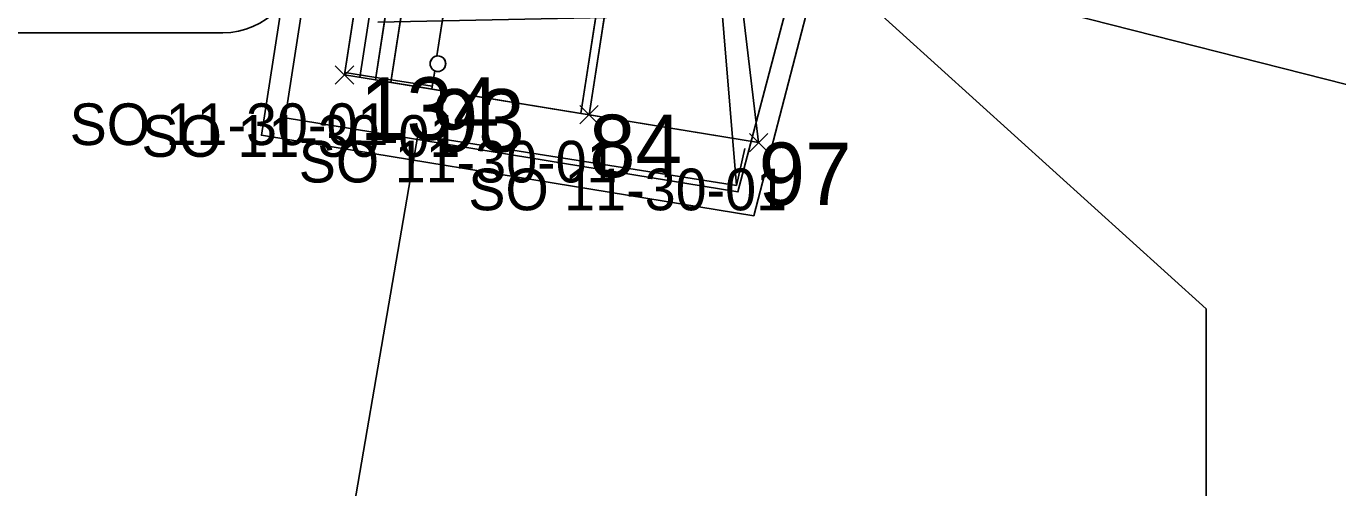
# Model space of a CAD drawing. Extents: x -728800 to -728100, y -1073200 to -1072700.
# Drawn here: x -728506.62 to -728494.02, y -1073056.81 to -1073052.38 of the extents above; entities that cross this region are included whole.
import ezdxf

# ---------------------------------------------------------------- set-up
doc = ezdxf.new("R2010")
doc.units = 0
for name, color, linetype in [('_NOR-návrh tenká', 7, 'Continuous'), ('_NOR-VDZ', 7, 'Continuous'), ('_NOR-šraf_+6', 7, 'Continuous'), ('_NOR-šraf_bezbariéra', 7, 'Continuous'), ('_NOR-šraf_chodník', 7, 'Continuous'), ('_NOR-šraf_varovný pás', 7, 'Continuous'), ('_NOR-šraf_vozovka', 7, 'Continuous'), ('_NOR-šraf_zeleň', 7, 'Continuous'), ('A1_OBVOD Spravy železnic', 7, 'Continuous'), ('A2_OBVOD STAVBY', 7, 'Continuous'), ('B1_body_poloha', 7, 'Continuous'), ('B2_body_číslo', 7, 'Continuous'), ('B3_body_popiska', 7, 'Continuous'), ('B6_JŽM', 7, 'Continuous'), ('KTA_členění PS a SO', 7, 'Continuous'), ('ZA_02_Dočasný_do_1_roku', 7, 'Continuous')]:
    doc.layers.add(name, color=color, linetype=linetype)

msp = doc.modelspace()

# ---------------------------------------------------------------- linework, layer by layer
at = {"layer": '_NOR-návrh tenká'}
for p, q in [((-728499.581, -1073053.497), (-728499.904, -1073050.807)), ((-728503.263, -1073052.895), (-728503.559, -1073052.847)), ((-728499.581, -1073053.497), (-728503.263, -1073052.895))]:
    msp.add_line(p, q, dxfattribs=at)
for points in [[(-728502.819, -1073048.076), (-728503.559, -1073052.847)], [(-728502.523, -1073048.119), (-728503.263, -1073052.895)], [(-728502.374, -1073048.141), (-728503.115, -1073052.92)], [(-728500.544, -1073048.409), (-728501.289, -1073053.218)], [(-728500.465, -1073048.422), (-728501.21, -1073053.23)], [(-728502.31, -1073050.336), (-728502.671, -1073052.666)], [(-728502.693, -1073052.808), (-728502.721, -1073052.984)]]:
    msp.add_lwpolyline(points, dxfattribs=at)
msp.add_circle((-728502.662, -1073052.74), 0.075, dxfattribs=at)
at = {"layer": '_NOR-VDZ'}
msp.add_lwpolyline([(-728502.671, -1073048.097), (-728503.411, -1073052.871)], dxfattribs=at)
at = {"layer": '_NOR-šraf_+6'}
for p, q in [((-728500.465, -1073048.422), (-728501.21, -1073053.231)), ((-728501.289, -1073053.218), (-728500.958, -1073051.084)), ((-728501.21, -1073053.231), (-728501.289, -1073053.218))]:
    msp.add_line(p, q, dxfattribs=at)
at = {"layer": '_NOR-šraf_bezbariéra'}
for p, q in [((-728503.259, -1073052.871), (-728502.523, -1073048.119)), ((-728502.374, -1073048.141), (-728503.111, -1073052.894)), ((-728503.111, -1073052.894), (-728503.259, -1073052.871)), ((-728503.259, -1073052.871), (-728503.111, -1073052.894))]:
    msp.add_line(p, q, dxfattribs=at)
msp.add_lwpolyline([(-728503.111, -1073052.894), (-728503.115, -1073052.92), (-728503.229, -1073052.901), (-728503.263, -1073052.895), (-728503.259, -1073052.871)], dxfattribs=at)
at = {"layer": '_NOR-šraf_chodník'}
for p, q in [((-728502.671, -1073052.666), (-728502.31, -1073050.336)), ((-728500.994, -1073051.315), (-728501.289, -1073053.218)), ((-728502.721, -1073052.984), (-728502.693, -1073052.808)), ((-728501.289, -1073053.218), (-728502.721, -1073052.984))]:
    msp.add_line(p, q, dxfattribs=at)
msp.add_arc((-728502.662, -1073052.74), 0.075, 245.3796, 96.9883, dxfattribs=at)
at = {"layer": '_NOR-šraf_varovný pás'}
msp.add_line((-728502.31, -1073050.336), (-728502.671, -1073052.666), dxfattribs=at)
for points in [[(-728502.693, -1073052.808), (-728502.716, -1073052.955), (-728503.111, -1073052.894), (-728502.409, -1073048.363)], [(-728503.115, -1073052.92), (-728503.111, -1073052.894), (-728502.716, -1073052.955), (-728502.721, -1073052.984), (-728503.115, -1073052.92)]]:
    msp.add_lwpolyline(points, dxfattribs=at)
msp.add_arc((-728502.662, -1073052.74), 0.075, 96.9883, 245.3796, dxfattribs=at)
at = {"layer": '_NOR-šraf_vozovka'}
for p, q in [((-728503.556, -1073052.825), (-728502.819, -1073048.076)), ((-728503.106, -1073051.882), (-728503.259, -1073052.871)), ((-728503.259, -1073052.871), (-728503.556, -1073052.825))]:
    msp.add_line(p, q, dxfattribs=at)
msp.add_lwpolyline([(-728503.556, -1073052.825), (-728503.259, -1073052.871), (-728503.263, -1073052.895), (-728503.559, -1073052.847), (-728503.556, -1073052.825)], dxfattribs=at)
at = {"layer": '_NOR-šraf_zeleň'}
for p, q in [((-728501.21, -1073053.231), (-728500.465, -1073048.422)), ((-728499.904, -1073050.807), (-728499.581, -1073053.497)), ((-728499.581, -1073053.497), (-728501.21, -1073053.231))]:
    msp.add_line(p, q, dxfattribs=at)
at = {"layer": 'A1_OBVOD Spravy železnic'}
msp.add_lwpolyline([(-728503.24, -1073052.34), (-728496.81, -1073052.21), (-728491.97, -1073053.44), (-728477.97, -1073053.19), (-728470.97, -1073054.08), (-728434.43, -1073049.27), (-728361.73, -1073039.5), (-728349.166, -1073038.984)], dxfattribs=at)
at = {"layer": 'A2_OBVOD STAVBY'}
msp.add_lwpolyline([(-728503.756, -1073049.547), (-728504.358, -1073053.426), (-728503.463, -1073053.572), (-728499.628, -1073054.199), (-728499.129, -1073052.28), (-728499.2, -1073051.021), (-728494.25, -1073049.503), (-728493.918, -1073046.515)], dxfattribs=at)
at = {"layer": 'B1_body_poloha'}
for p, q in [((-728503.648, -1073052.759), (-728503.471, -1073052.935)), ((-728503.648, -1073052.935), (-728503.471, -1073052.759)), ((-728501.298, -1073053.142), (-728501.122, -1073053.318)), ((-728501.298, -1073053.318), (-728501.122, -1073053.142)), ((-728499.669, -1073053.409), (-728499.493, -1073053.585)), ((-728499.669, -1073053.585), (-728499.493, -1073053.409))]:
    msp.add_line(p, q, dxfattribs=at)
at = {"layer": 'B2_body_číslo'}
for p, q in [((-728503.411, -1073052.871), (-728503.411, -1073052.871)), ((-728502.721, -1073052.984), (-728502.721, -1073052.984)), ((-728501.21, -1073053.23), (-728501.21, -1073053.23)), ((-728499.581, -1073053.497), (-728499.581, -1073053.497))]:
    msp.add_line(p, q, dxfattribs=at)
at = {"layer": 'B6_JŽM'}
for points in [[(-728499.794, -1073053.909), (-728500.162, -1073049.472), (-728499.558, -1073044.443)], [(-728506.273, -1073069.065), (-728505.797, -1073069.171), (-728505.457, -1073067.617), (-728502.232, -1073068.271), (-728502.075, -1073067.494), (-728505.291, -1073066.851), (-728503.761, -1073058.691), (-728502.856, -1073053.426), (-728499.794, -1073053.909), (-728499.714, -1073053.554)]]:
    msp.add_lwpolyline(points, dxfattribs=at)
at = {"layer": 'KTA_členění PS a SO'}
for p, q in [((-728495.283, -1073055.094), (-728501.186, -1073049.755)), ((-728495.283, -1073057.094), (-728495.283, -1073055.094))]:
    msp.add_line(p, q, dxfattribs=at)
msp.add_lwpolyline([(-728504.729, -1073052.444), (-728509.729, -1073052.444)], dxfattribs=at)
msp.add_arc((-728504.735, -1073051.694), 0.75, 270.4529, 89.5471, dxfattribs=at)
at = {"layer": 'ZA_02_Dočasný_do_1_roku'}
msp.add_lwpolyline([(-728502.83, -1073049.48), (-728503.528, -1073049.379), (-728504.13, -1073053.261), (-728499.78, -1073053.97), (-728499.33, -1073052.26)], dxfattribs=at)

# ---------------------------------------------------------------- texts
at = {"layer": 'B2_body_číslo'}
for s, p in [('134', (-728503.411, -1073053.471)), ('93', (-728502.721, -1073053.584)), ('84', (-728501.21, -1073053.83)), ('97', (-728499.581, -1073054.097))]:
    msp.add_text(s, height=0.6, dxfattribs=at).set_placement(p)
at = {"layer": 'B3_body_popiska'}
for p in [(-728506.2, -1073053.521), (-728505.51, -1073053.634), (-728503.999, -1073053.88), (-728502.37, -1073054.147)]:
    msp.add_text('SO 11-30-01', height=0.4, dxfattribs=at).set_placement(p)

doc.saveas('drawing.dxf')
